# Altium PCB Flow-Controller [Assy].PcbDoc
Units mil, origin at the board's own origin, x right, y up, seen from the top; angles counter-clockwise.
Board outline 3346.46 x 3543.31 mil, 2 copper layers (Top Layer, Bottom Layer), stack 61.855 mil thick; 0 components, 85 nets, 0 pads, 0 vias.
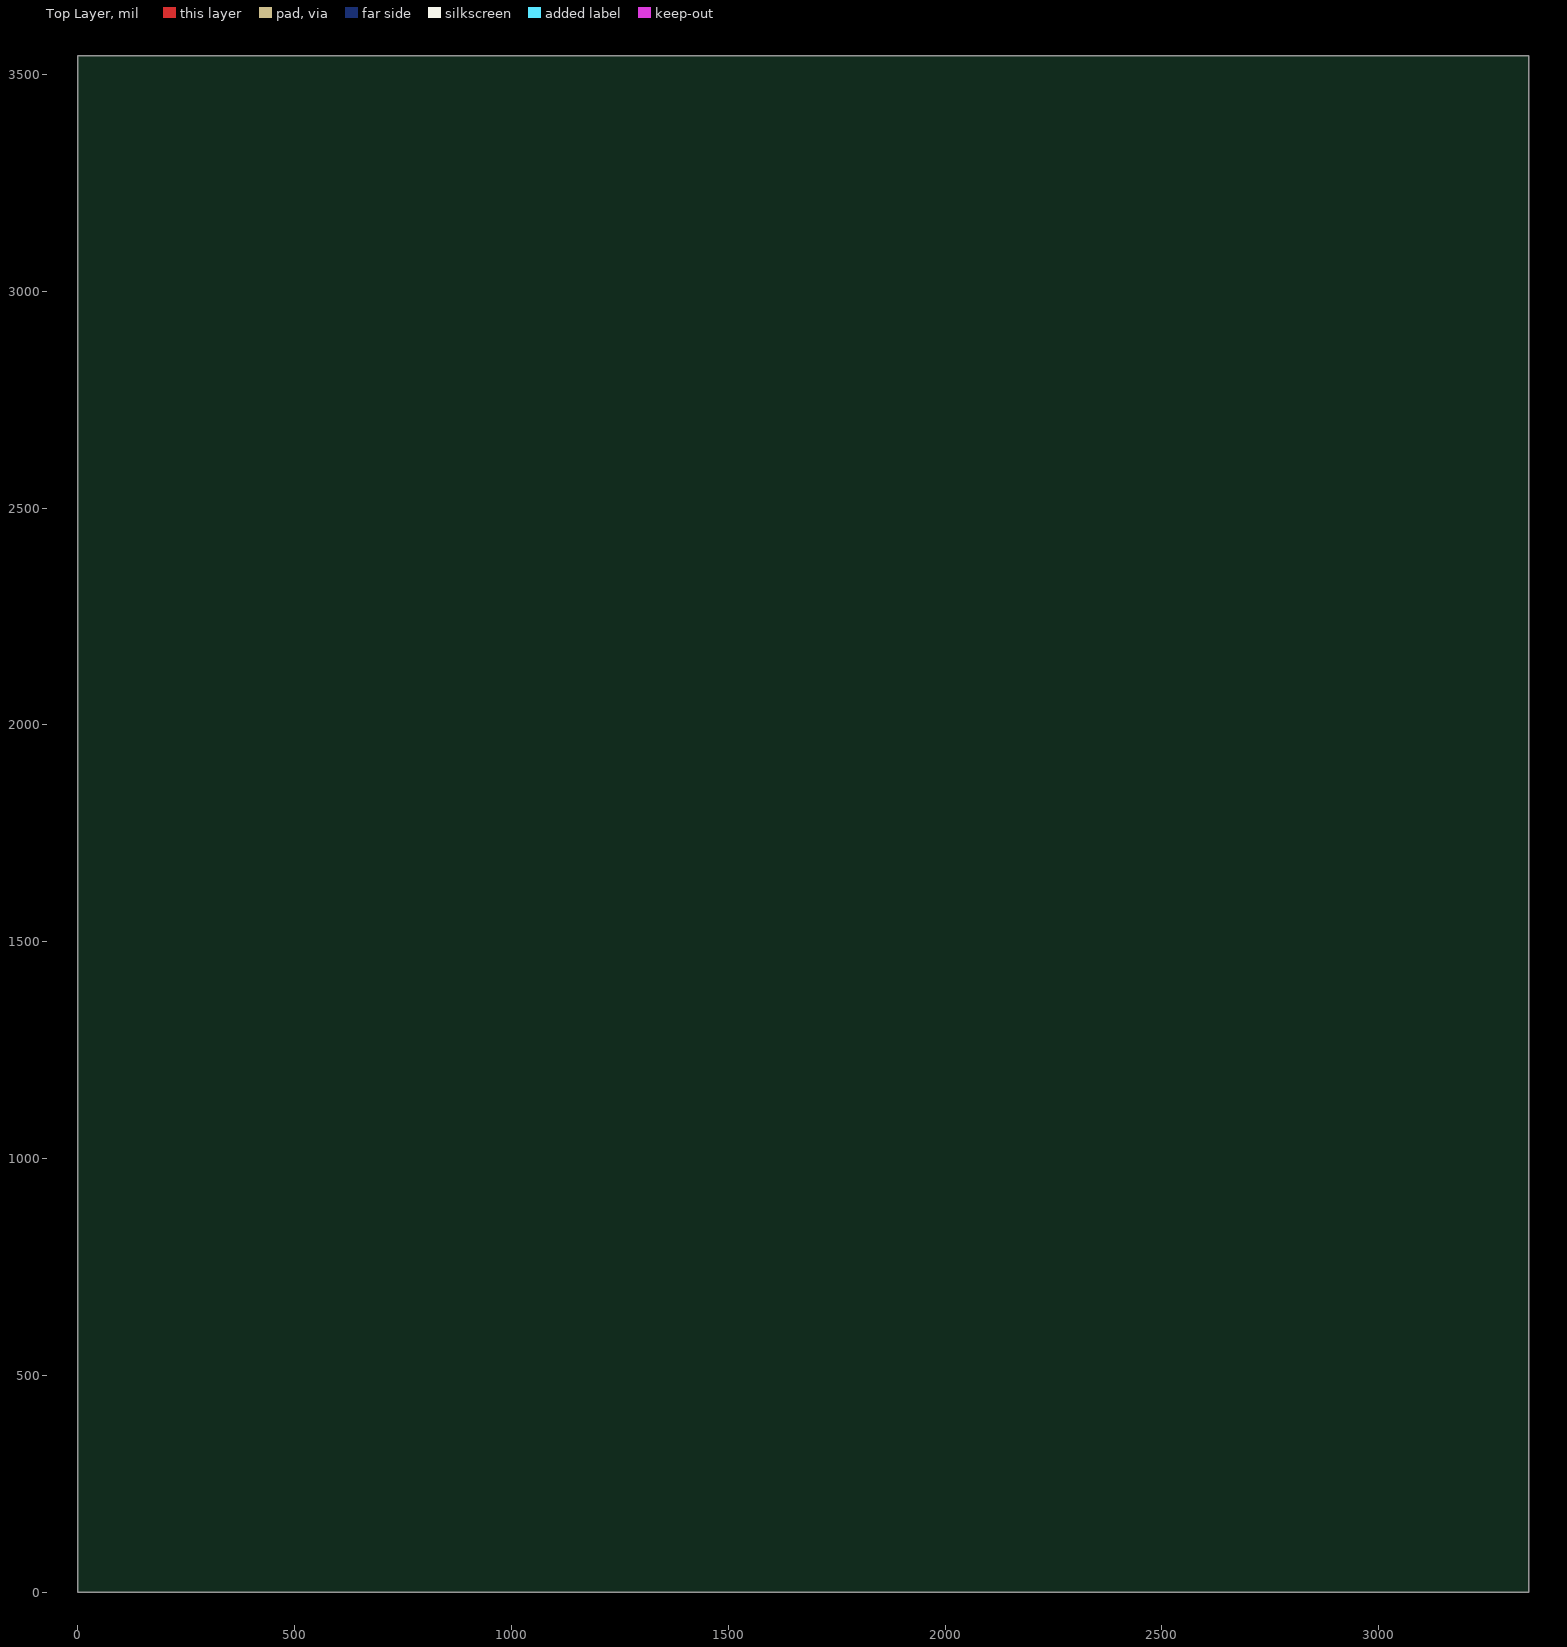
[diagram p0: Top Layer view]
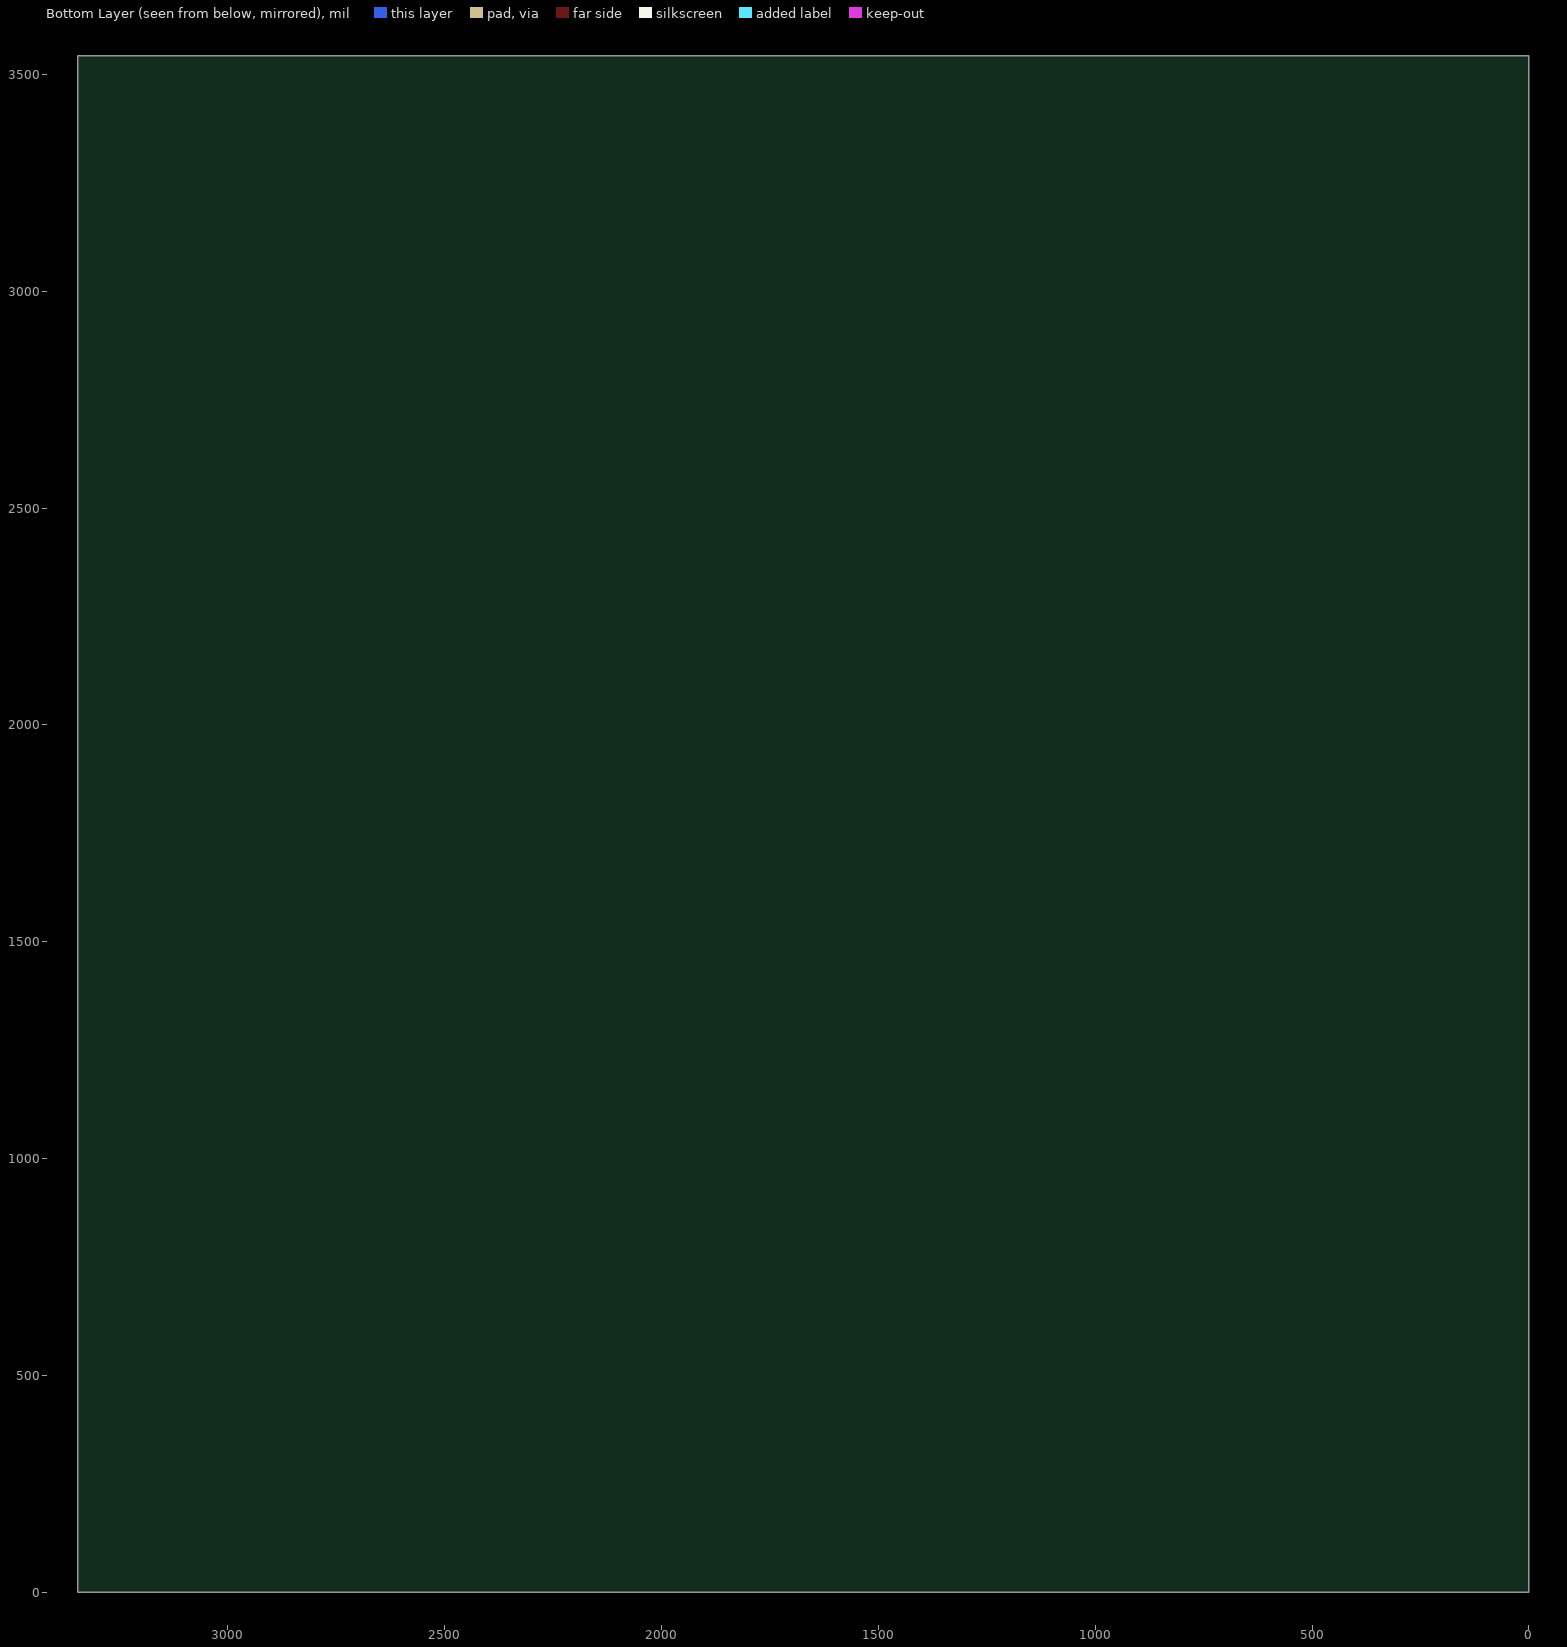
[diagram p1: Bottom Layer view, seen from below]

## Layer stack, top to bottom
Top Layer: signal copper 1.4
Dielectric: prepreg 59.0551, FR-4, Dk 4.2
Bottom Layer: signal copper 1.4

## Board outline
0,0 3346.46,0 3346.46,3543.31 0,3543.31

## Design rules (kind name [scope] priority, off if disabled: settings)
Clearance [All] p1: gap=6.69
ComponentClearance [All] p1: gap=0 collisioncheckmode=3 verticalgap=1 showdistances=FALSE
FabricationTestPointUsage TestPointUsage [All] p1: valid=0 allowmultiple=FALSE
FabricationTestpoint Testpoint [All] p1: side=3 testpointundercomponent=TRUE minsize=40 maxsize=100 preferedsize=60 minholesize=0 maxholesize=40 preferedholesize=32 testpointgrid=1 allowsidetop=TRUE allowsidebottom=TRUE usegrid=TRUE gridtolerance=0.01
HoleSize [All] p1: absolutevalues=TRUE maxlimit=196.85 minlimit=9.84 maxpercent=80.000 minpercent=20.000
PlaneClearance [All] p1: clearance=19.68
PolygonConnect PolygonConnect_8 [All vs IsNamedPolygon('Top - GND1-HSK')] p1: connectstyle=Direct reliefconductorwidth=10 reliefentries=4 polygonreliefangle="90 Angle" airgapwidth=10
PolygonConnect PolygonConnect_7 [All vs IsNamedPolygon('Bot - GND1-HSK')] p2: connectstyle=Direct reliefconductorwidth=10 reliefentries=4 polygonreliefangle="90 Angle" airgapwidth=10
PolygonConnect PolygonConnect_6 [All vs IsNamedPolygon('Bot - GND4a') Or  IsNamedPolygon('Bot - GND2a') Or  IsNamedPolygon('Bot - GND3a')] p3: connectstyle=Direct reliefconductorwidth=10 reliefentries=4 polygonreliefangle="90 Angle" airgapwidth=10
PolygonConnect PolygonConnect_5 [All vs IsNamedPolygon('Bot - GND1a')] p4: connectstyle=Direct reliefconductorwidth=10 reliefentries=4 polygonreliefangle="90 Angle" airgapwidth=10
PolygonConnect PolygonConnectVia [All vs isvia] p5: connectstyle=Direct reliefconductorwidth=9.84 reliefentries=4 polygonreliefangle="90 Angle" airgapwidth=10
PolygonConnect PolygonConnect_4 [All vs IsNamedPolygon('Bot - GND2')] p6: connectstyle=Relief reliefconductorwidth=30 reliefentries=4 polygonreliefangle="90 Angle" airgapwidth=10
PolygonConnect PolygonConnect_3 [All vs IsNamedPolygon('Bot - GND1')] p7: connectstyle=Relief reliefconductorwidth=30 reliefentries=4 polygonreliefangle="90 Angle" airgapwidth=10
PolygonConnect PolygonConnect_2 [All vs IsNamedPolygon('Bot - GND4')] p8: connectstyle=Relief reliefconductorwidth=30 reliefentries=4 polygonreliefangle="90 Angle" airgapwidth=10
PolygonConnect PolygonConnect_1 [All vs IsNamedPolygon('Bot - GND3')] p9: connectstyle=Relief reliefconductorwidth=30 reliefentries=4 polygonreliefangle="90 Angle" airgapwidth=10
PolygonConnect [All] p10: connectstyle=Relief reliefconductorwidth=15.75 reliefentries=4 polygonreliefangle="90 Angle" airgapwidth=10
RoutingCorners [All] p1: cornerstyle=45-Degree minsetback=98.43 maxsetback=98.43
RoutingVias [All] p1: holewidth=11.81 width=27.56 viastyle="Through Hole" minholewidth=11.81 minwidth=27.56 maxholewidth=11.81 maxwidth=27.56
ShortCircuit ShortCircuit_LK1 [(InComponent('LK1'))] p1: allowed=TRUE
ShortCircuit ShortCircuit_LK2 [(InComponent('LK2'))] p2: allowed=TRUE
ShortCircuit ShortCircuit_LK3 [(InComponent('LK3'))] p3: allowed=TRUE
ShortCircuit [All] p4: allowed=FALSE
SilkToSolderMaskClearance SilkscreenOverComponentPads [IsPad] p1: minsilkscreentomaskgap=10 clearancetoexposedcopper=TRUE
SolderMaskExpansion [All] p1: expansion=1.97
Width "Width_High Power" [InNetClass('High Power')] p1: maxlimit=59.06 minlimit=19.68 preferedwidth=39.37
Width Width_Power [InNetClass('Power')] p2: maxlimit=39.37 minlimit=11.81 preferedwidth=19.68
Width [All] p3: maxlimit=78.74 minlimit=7.87 preferedwidth=7.87
20 further rules are at their usual default settings.

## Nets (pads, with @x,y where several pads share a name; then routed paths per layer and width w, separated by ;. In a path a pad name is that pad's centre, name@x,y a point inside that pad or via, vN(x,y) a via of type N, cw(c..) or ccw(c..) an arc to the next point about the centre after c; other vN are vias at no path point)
485+: 
485-: 
+5V: 
BLACK: 
BLACK_M1: 
BLACK_M2: 
BLUE: 
DIR_A3979: 
FLOW_METER: 
GND1: 
GND2: 
GND3: 
GND4: 
GREEN: 
GREEN_LED: 
M_0: 
M_1: 
MCLR: 
MS_1: 
MS_2: 
NetC5_1: 
NetC5_2: 
NetC7_1: 
NetC8_1: 
NetC9_1: 
NetC10_1: 
NetC13_1: 
NetC14_1: 
NetC18_2: 
NetC19_1: 
NetC19_2: 
NetC20_1: 
NetC21_1: 
NetC22_1: 
NetC23_1: 
NetC24_1: 
NetC25_1: 
NetC26_1: 
NetC27_1: 
NetD1_1: 
NetD6_1: 
NetD7_1: 
NetJ1_1: 
NetJ1_2: 
NetJ2_1: 
NetJ2_2: 
NetJ2_3: 
NetJ2_4: 
NetLED1_2: 
NetLED2_2: 
NetP2_2: 
NetP2_3: 
NetP2_5: 
NetP2_6: 
NetQ1_1: 
NetR3_2: 
NetR14_2: 
NetR33_2: 
NetR34_2: 
NetR35_2: 
NetR43_2: 
NetR44_2: 
NetR46_1: 
NetR47_1: 
NetR50_2: 
NetR51_2: 
NetR53_1: 
PGC: 
PGD: 
RED: 
RED_LED: 
RED_M1: 
RED_M2: 
RESET_A3979: 
RX: 
SCL: 
SDA: 
SENSOR: 
SLEEP: 
STEP_A3979: 
TX: 
TX_EN: 
V+POWER: 
VCC: 
VIN: 

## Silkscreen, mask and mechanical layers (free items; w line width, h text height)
Top Assy 1:
  circle w4.92: c0.04,-0.63 r78.74
  circle w5: c385,4450 r30
  circle w5: c485,4550 r30
  circle w5: c385,4650 r30
  lines w5: 335,4350 335,4740 535,4740 535,4350 335,4350
  lines w7.87: -3182.44,-1961.3 -938.35,-1961.3 ; -2690.32,-2158.15 -2690.32,-1961.3 ; -938.35,-1764.45 2841.18,-1764.45 6423.86,-1764.45 ; -938.35,-1567.6 2841.18,-1567.6 ; -938.35,-1370.75 2841.18,-1370.75 ; -938.35,-1173.9 2841.18,-1173.9 ; -590.51,393.07 -511.77,393.07 ; -590.51,786.77 -511.77,786.77 ; -590.51,1179.37 -590.51,3935 ; -590.51,1180.47 -511.77,1180.47 ; -590.51,1574.17 -511.77,1574.17 ; -590.51,1967.87 -511.77,1967.87 ; -590.51,2361.58 -511.77,2361.58 ; -590.51,2755 -590.51,-0.63 -511.77,-0.63 ; -590.51,2755.28 -511.77,2755.28 ; -590.51,3147.87 -511.77,3147.87 ; -590.51,3541.58 -511.77,3541.58 ; -590.51,3935.28 -511.77,3935.28 ; -308.43,-2158.15 -308.43,-977.05 ; -118.07,-0.63 -39.33,-0.63 ; 0.04,-512.44 0.04,-591.18 3540,-591.18 ; 0.04,-118.74 0.04,-40 ; 321.5,-977.05 321.5,-2158.15 321.5,-1961.3 ; 393.74,-591.18 393.74,-512.44 ; 787.44,-591.18 787.44,-512.44 ; 951.42,-2158.15 951.42,-977.05 ; 1181.14,-591.18 1181.14,-512.44 ; 1574.84,-591.18 1574.84,-512.44 ; 1581.34,-2158.15 1581.34,-977.05 ; 1968.54,-591.18 1968.54,-512.44 ; 2211.26,-2158.15 2211.26,-977.05 ; 2362.24,-591.18 2362.24,-512.44 ; 2755.94,-591.18 2755.94,-512.44 ; 3149.65,-591.18 3149.65,-512.44 ; 3543.35,-591.18 3543.35,-512.44 ; 3549.84,-2158.15 3549.84,-1764.45 ; 5045.9,-2158.15 5045.9,-1764.45 ; 5557.72,-2158.15 5557.72,-1764.45 ; 6423.86,-1961.3 2841.18,-1961.3 2211.26,-1961.3 1581.34,-1961.3 951.42,-1961.3 321.5,-1961.3 ; -938.35,-2158.15 -938.35,-1961.3 ; -938.35,-2158.15 -938.35,-1961.3 ; -938.35,-2158.15 -938.35,-1961.3 ; -938.35,-1961.3 -308.43,-1961.3 321.5,-1961.3 ; -938.35,-1961.3 -938.35,-977.05 ; -938.35,-977.05 2841.18,-977.05 ; -938.35,-977.05 -1568.27,-977.05 -3182.44,-977.05 -3182.44,-2158.15 2841.18,-2158.15 ; 2841.18,-2158.15 6423.86,-2158.15 6423.86,-977.05 2841.18,-977.05 ; 2841.18,-2158.15 2841.18,-977.05
  text "ASSEMBLY INSTRUCTIONS" at 25,4925 h150
  text "1. DO NOT FIT R35" at 600,4650 h150
  text "1" at 375,4630 h60
  text "2" at 475,4530 h60
  text "1." at 25,4500 h150
  text "2. FIT RESISTOR 6K73 OHM 1%, BETWEEN PINS 1 AND 2" at 600,4500 h150
  text "R35" at 300,4475 h90 r90
  text "3" at 375,4430 h60
  text "3. FIT RESISTOR 2K94 OHM 1%, BETWEEN PINS 2 AND 3" at 600,4350 h150
  text "2." at 25,4025 h150
  text "PLEASE MARK THE \"ISSUE\" BLOCK, ON THE PCB, WITH A" at 260,4025 h150
  text "100" at -472.4,3895.91 h98.43
  text "PERMANENT-MARKER, AS INDICATED BELOW:" at 260,3875 h150
  text "ISSUE:" at 254.16,3725 h150
  text ".Version_PCB Assy Instruction" at 724.16,3718.43 h157.48
  text "90" at -472.4,3502.21 h98.43
  text "80" at -472.4,3108.5 h98.43
  text "70" at -472.4,2715.91 h98.43
  text "60" at -472.4,2322.21 h98.43
  text "50" at -472.4,1928.5 h98.43
  text "40" at -472.4,1534.8 h98.43
  text "30" at -472.4,1141.1 h98.43
  text "20" at -472.4,747.4 h98.43
  text "10" at -472.4,353.7 h98.43
  text "0" at -472.4,-40 h98.43
  text "0" at 39.41,-473.07 h98.43 r90
  text "10" at 433.11,-473.07 h98.43 r90
  text "20" at 826.81,-473.07 h98.43 r90
  text "30" at 1220.51,-473.07 h98.43 r90
  text "40" at 1614.21,-473.07 h98.43 r90
  text "50" at 2007.91,-473.07 h98.43 r90
  text "60" at 2401.61,-473.07 h98.43 r90
  text "70" at 2795.31,-473.07 h98.43 r90
  text "80" at 3189.02,-473.07 h98.43 r90
  text "90" at 3582.72,-473.07 h98.43 r90
  text "TITLE" at 2919.92,-1095.16 h98.43
  text "AGRIGEL" at -3016.12,-1348.07 h393.7
  text ".PCB_TITLE" at 3038.03,-1410.12 h196.85
  text "TOP SIDE PLACEMENT" at 3038.03,-1567.6 h98.43
  text ".PCB_Drawn" at -780.87,-1882.56 h98.43
  text ".PCB_Checked" at -190.32,-1882.56 h98.43
  text ".PCB_Approved" at 439.61,-1882.56 h98.43
  text ".PRINT_DATE" at 1069.53,-1882.56 h98.43
  text ".PCB_DocRevision" at 1825,-1882.56 h98.43
  text ".PCB_ECRNo" at 2368.74,-1882.56 h98.43
  text "DWG NUMBER" at 2880.55,-1882.56 h98.43
  text ".PCB_Drawing Number" at 3628.58,-1882.56 h98.43
  text "PCB VER" at 5085.27,-1882.56 h98.43
  text "SHEET NO." at 5636.46,-1882.56 h98.43
  text "PLOTFILE" at -3143.07,-2079.41 h98.43
  text ".PCB_Plot File [Assy]" at -2650.95,-2079.41 h98.43
  text "DRAWN" at -780.87,-2079.41 h98.43
  text "CHECKED" at -190.32,-2079.41 h98.43
  text "APPROVED" at 400.24,-2079.41 h98.43
  text "DATE" at 1148.27,-2079.41 h98.43
  text "DOC REV." at 1699.45,-2079.41 h98.43
  text "ECR NO." at 2368.74,-2079.41 h98.43
  text "SOURCE" at 2880.55,-2079.41 h98.43
  text ".Pcb_File_Name_No_Path" at 3628.58,-2079.41 h98.43
  text ".Version" at 5164.01,-2079.41 h98.43
  text "SHEET" at 5636.46,-2079.41 h98.43
  text "1" at 5990.79,-2079.41 h98.43
  text "OF" at 6108.9,-2079.41 h98.43
  text "2" at 6305.75,-2079.41 h98.43
Bot Assy 1:
  circle w4.92: c0.04,-0.63 r78.74
  lines w7.87: -3182.44,-1961.3 400.24,-1961.3 1030.16,-1961.3 1660.08,-1961.3 2290,-1961.3 2919.92,-1961.3 ; -3182.44,-1764.45 400.24,-1764.45 4179.76,-1764.45 ; -2316.3,-2158.15 -2316.3,-1764.45 ; -1804.49,-2158.15 -1804.49,-1764.45 ; -590.51,393.07 -511.77,393.07 ; -590.51,786.77 -511.77,786.77 ; -590.51,1179.37 -590.51,3936 ; -590.51,1180.47 -511.77,1180.47 ; -590.51,1574.17 -511.77,1574.17 ; -590.51,1967.87 -511.77,1967.87 ; -590.51,2361.58 -511.77,2361.58 ; -590.51,2755.28 -511.77,2755.28 ; -590.51,2756 -590.51,-0.63 -511.77,-0.63 ; -590.51,3147.87 -511.77,3147.87 ; -590.51,3541.58 -511.77,3541.58 ; -590.51,3935.28 -511.77,3935.28 ; -308.43,-2158.15 -308.43,-1764.45 ; -118.07,-0.63 -39.33,-0.63 ; 0.04,-512.44 0.04,-591.18 3540,-591.18 ; 0.04,-118.74 0.04,-40 ; 393.74,-591.18 393.74,-512.44 ; 400.24,-1567.6 4179.76,-1567.6 ; 400.24,-1370.75 4179.76,-1370.75 ; 400.24,-1173.9 4179.76,-1173.9 ; 787.44,-591.18 787.44,-512.44 ; 1030.16,-2158.15 1030.16,-977.05 ; 1181.14,-591.18 1181.14,-512.44 ; 1574.84,-591.18 1574.84,-512.44 ; 1660.08,-2158.15 1660.08,-977.05 ; 1968.54,-591.18 1968.54,-512.44 ; 2290,-2158.15 2290,-977.05 ; 2362.24,-591.18 2362.24,-512.44 ; 2755.94,-591.18 2755.94,-512.44 ; 2919.92,-977.05 2919.92,-2158.15 2919.92,-1961.3 ; 3149.65,-591.18 3149.65,-512.44 ; 3543.35,-591.18 3543.35,-512.44 ; 3549.84,-2158.15 3549.84,-977.05 ; 5931.73,-2158.15 5931.73,-1961.3 ; 6423.86,-1961.3 4179.76,-1961.3 ; 400.24,-2158.15 6423.86,-2158.15 6423.86,-977.05 4809.68,-977.05 4179.76,-977.05 ; 400.24,-2158.15 400.24,-977.05 ; 400.24,-2158.15 -3182.44,-2158.15 -3182.44,-977.05 400.24,-977.05 ; 400.24,-977.05 4179.76,-977.05 ; 2919.92,-1961.3 3549.84,-1961.3 4179.76,-1961.3 ; 4179.76,-2158.15 4179.76,-1961.3 ; 4179.76,-2158.15 4179.76,-1961.3 ; 4179.76,-2158.15 4179.76,-1961.3 ; 4179.76,-1961.3 4179.76,-977.05
  text "100" at -360,3900 h98.43
  text "90" at -383.82,3502.21 h98.43
  text "80" at -383.82,3108.5 h98.43
  text "70" at -383.82,2715.91 h98.43
  text "60" at -383.82,2322.21 h98.43
  text "50" at -383.82,1928.5 h98.43
  text "40" at -373.98,1534.8 h98.43
  text "30" at -383.82,1141.1 h98.43
  text "20" at -383.82,747.4 h98.43
  text "10" at -393.66,353.7 h98.43
  text "0" at -433.03,-40 h98.43
  text "40" at 1614.21,-374.64 h98.43 r90
  text "10" at 433.11,-384.49 h98.43 r90
  text "20" at 816.97,-384.49 h98.43 r90
  text "30" at 1220.51,-384.49 h98.43 r90
  text "50" at 2007.91,-384.49 h98.43 r90
  text "60" at 2401.61,-384.49 h98.43 r90
  text "70" at 2795.31,-384.49 h98.43 r90
  text "80" at 3189.02,-384.49 h98.43 r90
  text "90" at 3582.72,-384.49 h98.43 r90
  text "0" at 29.57,-433.7 h98.43 r90
  text "TITLE" at 321.5,-1095.16 h98.43
  text "AGRIGEL" at 6257.54,-1348.07 h393.7
  text ".PCB_TITLE" at 203.38,-1410.12 h196.85
  text "TOP SIDE PLACEMENT" at 203.38,-1567.6 h98.43
  text "SHEET NO." at -2395.04,-1882.56 h98.43
  text "PCB VER" at -1843.86,-1882.56 h98.43
  text ".PCB_Drawing Number" at -387.17,-1882.56 h98.43
  text "DWG NUMBER" at 360.87,-1882.56 h98.43
  text ".PCB_ECRNo" at 872.68,-1882.56 h98.43
  text ".PCB_DocRevision" at 1400,-1882.56 h98.43
  text ".PRINT_DATE" at 2171.89,-1882.56 h98.43
  text ".PCB_Approved" at 2801.81,-1882.56 h98.43
  text ".PCB_Checked" at 3431.73,-1882.56 h98.43
  text ".PCB_Drawn" at 4022.28,-1882.56 h98.43
  text "2" at -3064.33,-2079.41 h98.43
  text "OF" at -2867.48,-2079.41 h98.43
  text "2" at -2749.37,-2079.41 h98.43
  text "SHEET" at -2395.04,-2079.41 h98.43
  text ".Version" at -1922.6,-2079.41 h98.43
  text ".Pcb_File_Name_No_Path" at -387.17,-2079.41 h98.43
  text "SOURCE" at 360.87,-2079.41 h98.43
  text "ECR NO." at 872.68,-2079.41 h98.43
  text "DOC REV." at 1541.97,-2079.41 h98.43
  text "DATE" at 2093.15,-2079.41 h98.43
  text "APPROVED" at 2841.18,-2079.41 h98.43
  text "CHECKED" at 3431.73,-2079.41 h98.43
  text "DRAWN" at 4022.28,-2079.41 h98.43
  text ".PCB_Plot File [Assy]" at 5892.36,-2079.41 h98.43
  text "PLOTFILE" at 6384.49,-2079.41 h98.43

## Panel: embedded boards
"Flow-Controller.PcbDoc" at 0,0, 1 rows x 1 columns, spacing 2500 x 1500, rotation 0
